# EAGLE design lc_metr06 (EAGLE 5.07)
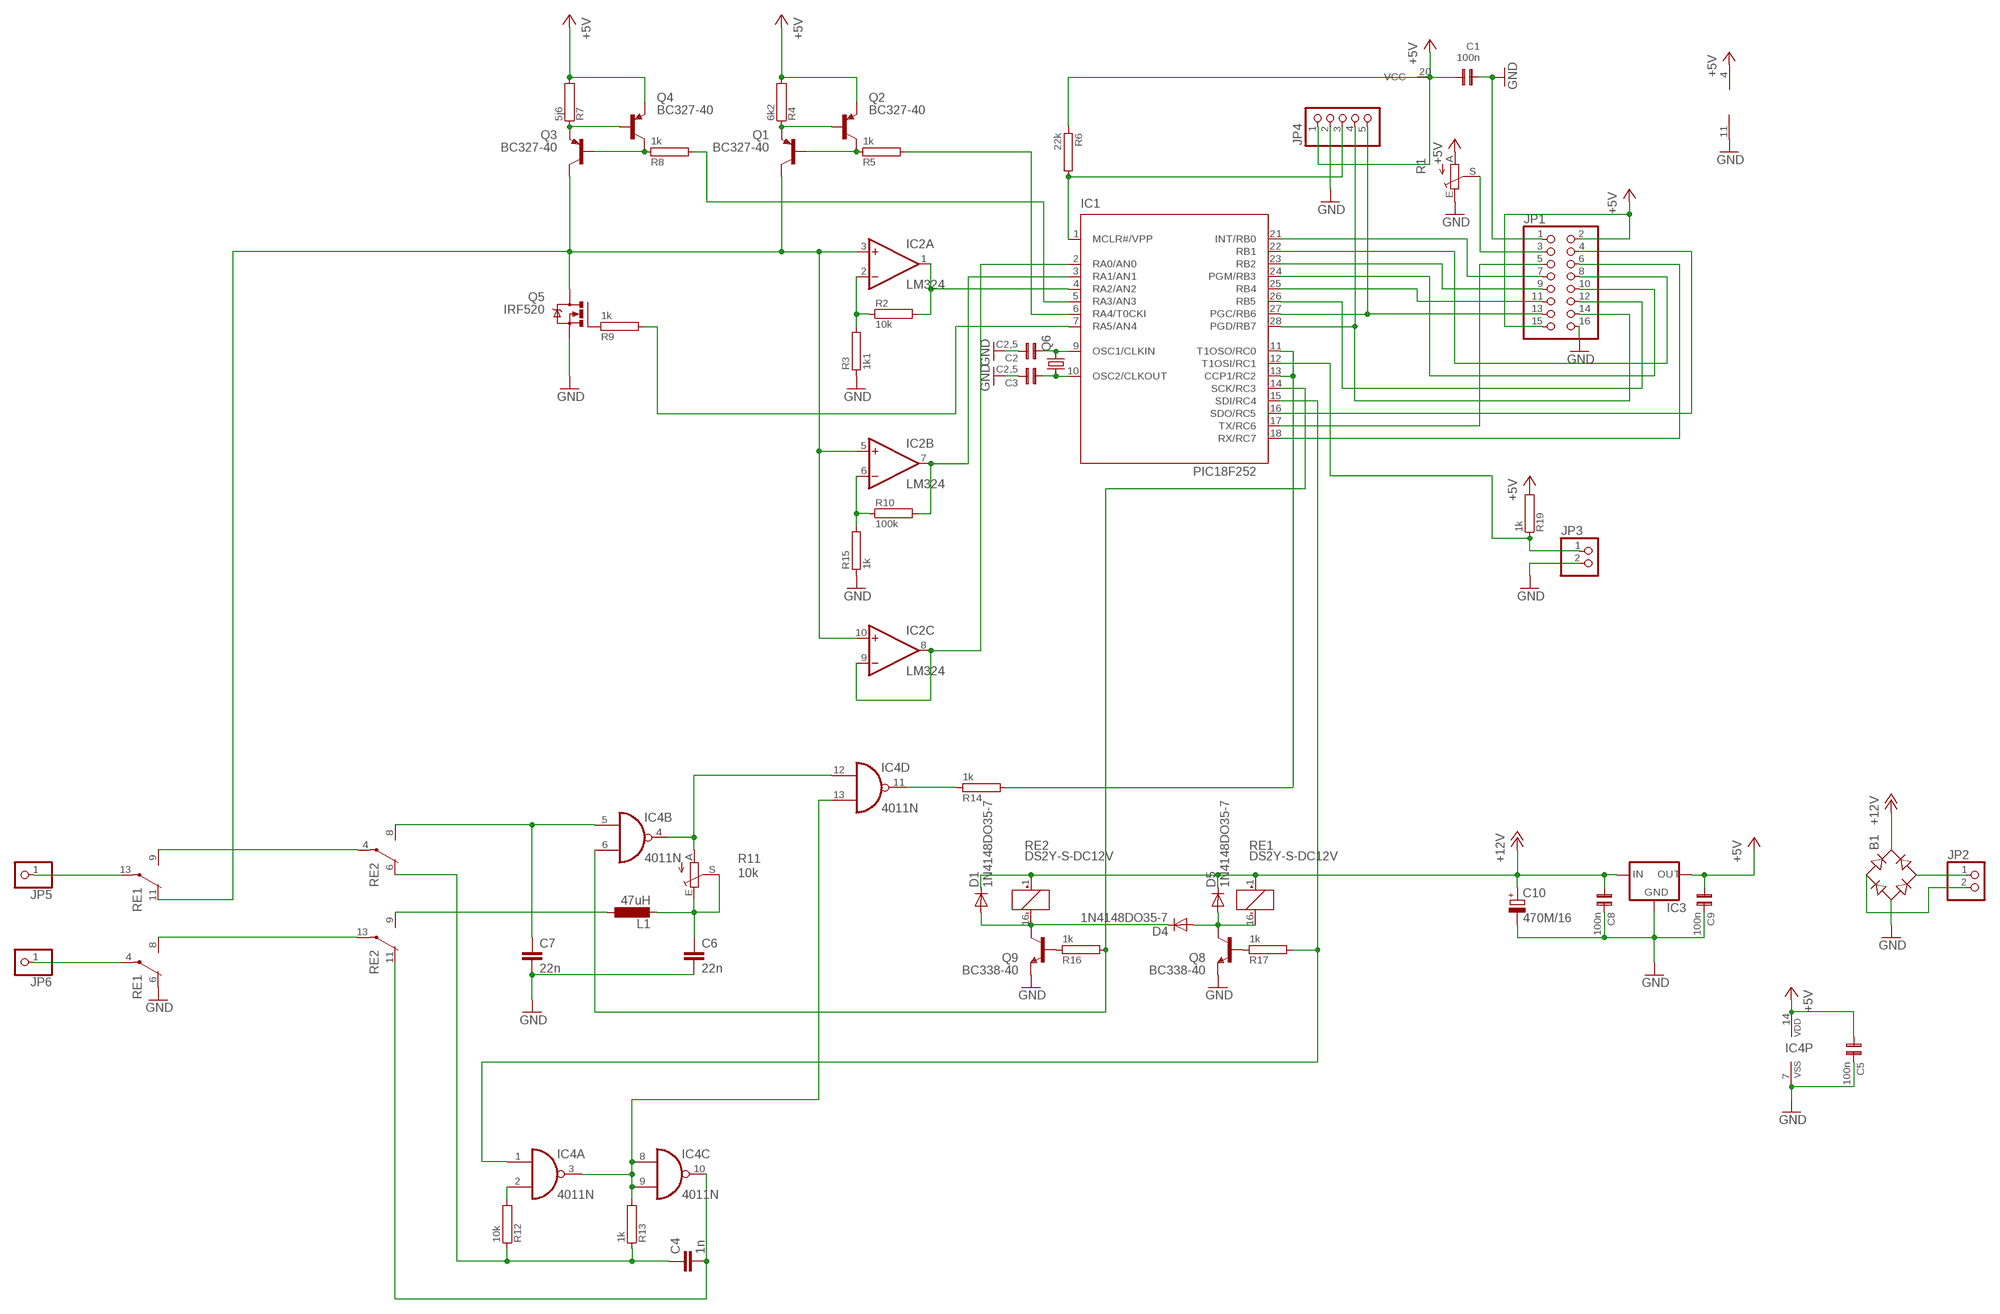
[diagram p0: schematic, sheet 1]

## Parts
B1  B-DIL  [B-DIL]
C1  100n  C2,5  [C2,5-4]
C2  C2,5  [C2,5-4]
C3  C2,5  [C2,5-4]
C4  1n  C-EU050-035X075  [C050-035X075]
C5  100n  C2,5  [C2,5-4]
C6  22n  C-EU050-035X075  [C050-035X075]
C7  22n  C-EU050-035X075  [C050-035X075]
C8  100n  C2,5  [C2,5-4]
C9  100n  C2,5  [C2,5-4]
C10  470M/16  CPOL-EUE5-10.5  [E5-10,5]
D1  1N4148DO35-7  [DO35-7]
D4  1N4148DO35-7  [DO35-7]
D5  1N4148DO35-7  [DO35-7]
IC1  PIC18F252  PIC18C252SP  [DIL28-3]
IC2  LM324  LF347N  [DIL14]
IC3  78XXS  [78XXS]
IC4  4011N  [DIL14]
JP1  PINHD-2X8  [2X08]
JP2  PINHD-1X2  [1X02]
JP3  PINHD-1X2  [1X02]
JP4  PINHD-1X5  [1X05]
JP5  PINHD-1X1  [1X01]
JP6  PINHD-1X1  [1X01]
L1  47uH  L-EUIR-2  [IR-2]
Q1  BC327-40  [TO92-EBC]
Q2  BC327-40  [TO92-EBC]
Q3  BC327-40  [TO92-EBC]
Q4  BC327-40  [TO92-EBC]
Q5  IRF520  [TO220BV]
Q6  CRYTALHC49U70  [HC49U70]
Q8  BC338-40  [TO92-EBC]
Q9  BC338-40  [TO92-EBC]
R1  TRIM_EU-ECP10S  [ECP10S]
R2  10k  0204/7  [0204/7]
R3  1k1  0204/7  [0204/7]
R4  6k2  0204/7  [0204/7]
R5  1k  0204/7  [0204/7]
R6  22k  0204/7  [0204/7]
R7  5j6  0204/7  [0204/7]
R8  1k  0204/7  [0204/7]
R9  1k  0204/7  [0204/7]
R10  100k  0204/7  [0204/7]
R11  10k  TRIM_EU-ECP10S  [ECP10S]
R12  10k  0204/7  [0204/7]
R13  1k  0204/7  [0204/7]
R14  1k  0204/7  [0204/7]
R15  1k  0204/7  [0204/7]
R16  1k  0204/7  [0204/7]
R17  1k  0204/7  [0204/7]
R19  1k  0204/7  [0204/7]
RE1  DS2Y-S-DC12V  [DS2Y]
RE2  DS2Y-S-DC12V  [DS2Y]

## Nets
+5V: C1.2 C5.1 C9.1 IC1.20(VCC) IC2.4(P:V+) IC3.OUT IC4.14(P:VDD) JP1.2 JP1.15 JP4.1 Q2.E Q4.E R1.A R4.2 R6.1 R7.2 R19.2
+12V: B1.+ C8.1 C10.+ D1.C D5.C IC3.IN RE1.1(1:+) RE2.1(1:+)
GND: B1.- C1.1 C2.2 C3.2 C5.2 C6.2 C7.2 C8.2 C9.2 C10.- IC2.11(P:V-) IC3.GND IC4.7(P:VSS) JP1.1 JP1.16 JP3.2 JP4.2 Q5.S Q8.E Q9.E R1.E R3.1 R15.1 RE1.6(2:O)
N$1: IC1.1(MCLR#/VPP) JP4.3 R6.2
N$2: JP1.3 R1.S
N$3: IC1.27(PGC/RB6) JP1.13 JP4.5
N$4: IC1.16(SDO/RC5) JP1.4
N$5: IC1.17(TX/RC6) JP1.5
N$6: IC1.18(RX/RC7) JP1.6
N$7: IC1.21(INT/RB0) JP1.7
N$8: IC1.22(RB1) JP1.8
N$9: IC1.23(RB2) JP1.9
N$10: IC1.26(RB5) JP1.12
N$11: IC1.28(PGD/RB7) JP1.14 JP4.4
N$12: IC1.24(PGM/RB3) JP1.10
N$13: IC1.25(RB4) JP1.11
N$14: IC2.2(A:-IN) R2.1 R3.2
N$15: IC1.4(RA2/AN2) IC2.1(A:OUT) R2.2
N$16: Q1.E Q2.B R4.1
N$17: Q1.B Q2.C R5.1
N$18: Q3.E Q4.B R7.1
N$19: Q3.B Q4.C R8.1
N$20: IC4.11(D:O) R14.1
N$21: IC1.6(RA4/T0CKI) R5.2
N$22: IC1.5(RA3/AN3) R8.2
N$23: Q5.G R9.1
N$24: IC1.7(RA5/AN4) R9.2
N$26: C6.1 L1.2 R11.E R11.S
N$27: IC1.11(T1OSO/RC0) IC1.13(CCP1/RC2) R14.2
N$28: IC2.6(B:-IN) R10.1 R15.2
N$29: IC1.3(RA1/AN1) IC2.7(B:OUT) R10.2
N$30: RE1.9(3:S) RE2.4(2:P)
N$31: RE1.8(2:S) RE2.13(3:P)
N$32: C2.1 IC1.9(OSC1/CLKIN) Q6.2
N$33: C3.1 IC1.10(OSC2/CLKOUT) Q6.1
N$34: C7.1 IC4.5(B:I0) RE2.8(2:S)
N$35: L1.1 RE2.9(3:S)
N$36: IC4.4(B:O) IC4.12(D:I0) R11.A
N$37: IC2.3(A:+IN) IC2.5(B:+IN) IC2.10(C:+IN) Q1.C Q3.C Q5.D RE1.11(3:O)
N$38: D4.A D5.A Q8.C RE1.16(1:-)
N$39: D1.A D4.C Q9.C RE2.16(1:-)
N$40: IC1.12(T1OSI/RC1) JP3.1 R19.1
N$41: B1.AC2 JP2.1
N$42: Q9.B R16.1
N$43: Q8.B R17.1
N$45: IC1.15(SDI/RC4) IC4.1(A:I0) R17.2
N$46: IC1.14(SCK/RC3) IC4.6(B:I1) R16.2
N$47: IC1.2(RA0/AN0) IC2.8(C:OUT) IC2.9(C:-IN)
N$48: B1.AC1 JP2.2
N$64: IC4.3(A:O) IC4.8(C:I0) IC4.9(C:I1) IC4.13(D:I1) R13.2
N$65: C4.2 IC4.10(C:O) RE2.11(3:O)
N$66: IC4.2(A:I1) R12.2
N$67: C4.1 R12.1 R13.1 RE2.6(2:O)
N$70: JP6.1 RE1.4(2:P)
N$71: JP5.1 RE1.13(3:P)
Unconnected: IC2.12(D:+IN) IC2.13(D:-IN) IC2.14(D:OUT)

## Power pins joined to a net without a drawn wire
GND: IC1.8(GND) IC1.19(GND)

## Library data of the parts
B1 = rectifier:B-DIL: RECTIFIER
C1-C3 C5 C8 C9 = CAP:C2,5
C4 C6 C7 = rcl:C-EU: CAPACITOR, European symbol
C10 = rcl:CPOL-EU: POLARIZED CAPACITOR, European symbol
D1 D4 D5 = diode:1N4148: DIODE
IC1 = micro-pic18xxx:PIC18C2*2?: High-Performance Microcontrollers with 10-Bit A/D
IC2 = linear:LF347: OP AMP
IC3 = v-reg:78XXS: VOLTAGE REGULATOR
IC4 = 40xx:4011: Quad 2-input NAND
JP1 = pinhead:PINHD-2X8: PIN HEADER
JP2 JP3 = pinhead:PINHD-1X2: PIN HEADER
JP4 = pinhead:PINHD-1X5: PIN HEADER
JP5 JP6 = pinhead:PINHD-1X1: PIN HEADER
L1 = rcl:L-EU: INDUCTOR, European symbol
Q1-Q4 = transistor-pnp:BC327*: PNP Transistror
Q5 = transistor-power:IRF520: HEXFET Power MOSFET
Q6 = crystal:CRYTAL: CRYSTAL
Q8 Q9 = transistor-npn:BC338*: NPN Transistor
R1 R11 = pot:TRIM_EU-: POTENTIOMETER
R2-R10 R12-R17 R19 = R:0204/7
RE1 RE2 = relay:DS2Y-S-DC*: MINIATURE RELAY NAiS Source: http://www.mew-europe.com/.. en_ds_61005_0023.pdf

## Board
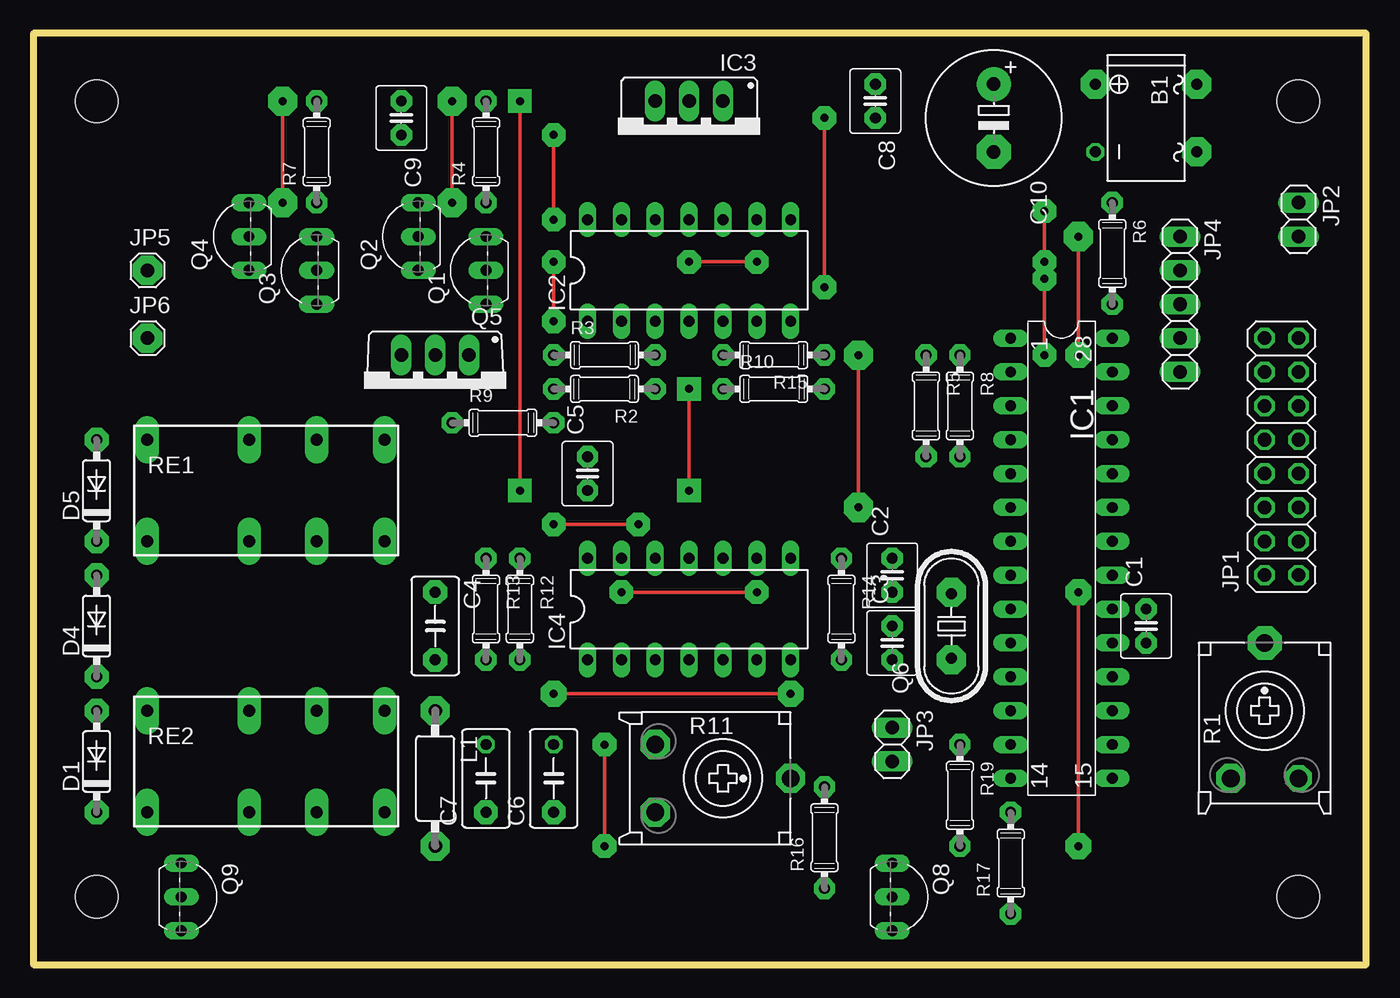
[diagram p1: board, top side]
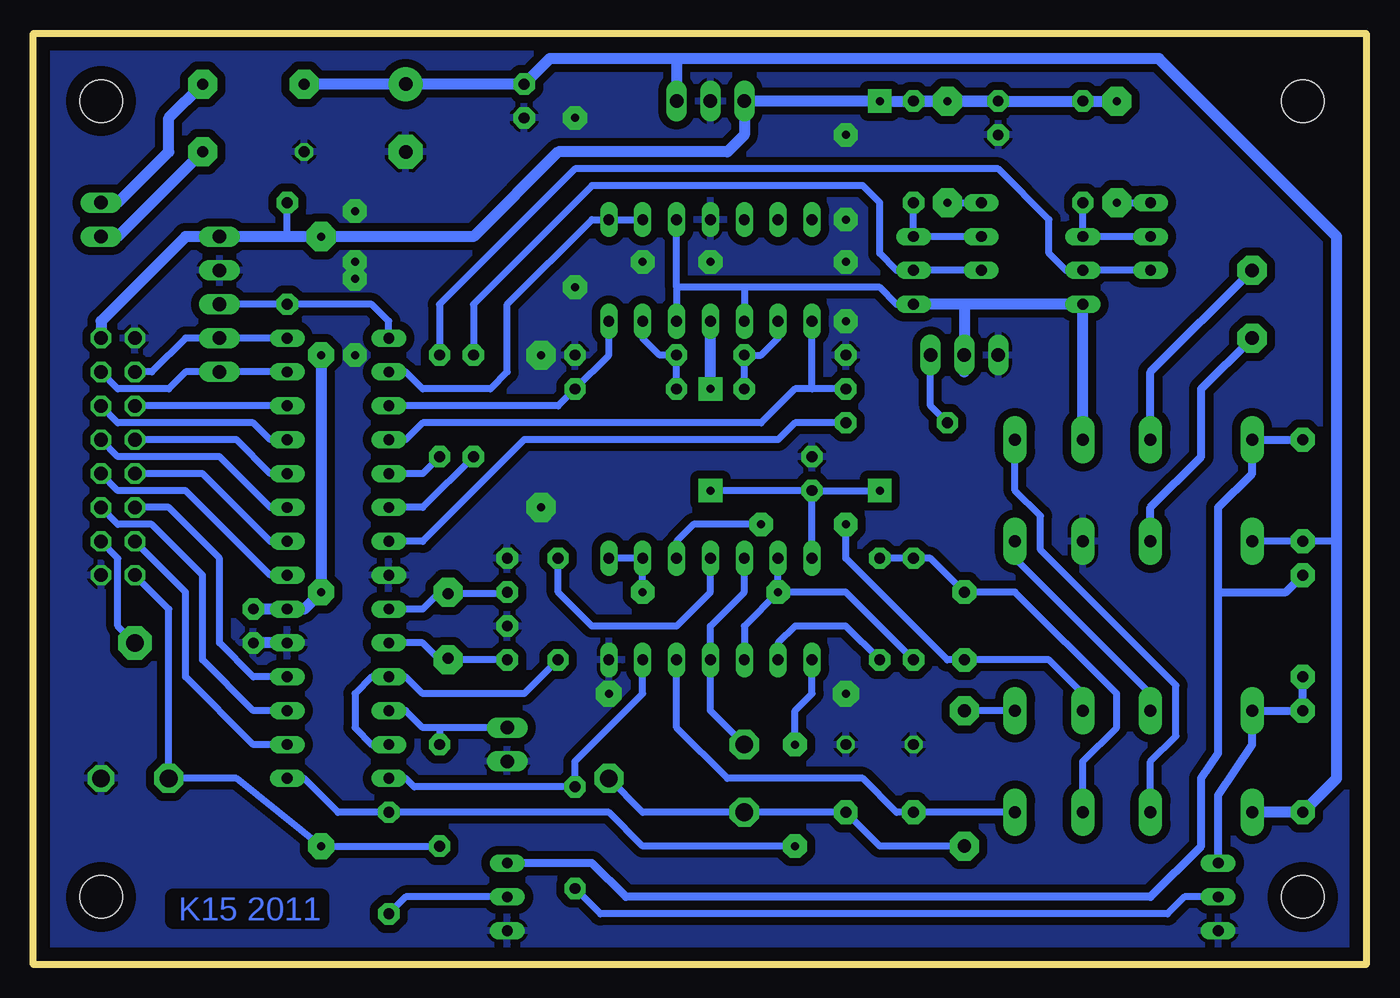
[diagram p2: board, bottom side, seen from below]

Size 100 x 69.84 mm. Coordinates in mm from the lower left corner, seen from the top.
Outline: 100,69.84 0,69.84 0,0 100,0 100,69.84
Copper layers (1*16): Top 0.035mm / dielectric 1.5mm / Bottom 0.035mm
Design rules "default": minimum track width 10mil, minimum drill 24mil, track to track 8mil, track to pad 8mil, pad to pad 8mil, via to via 8mil, smd to smd 8mil, copper to edge 40mil, drill to drill 8mil, minimum pad ring 10mil, minimum via ring 8mil, stop-mask expansion 4mil, vias tented up to drill 0mil, thermal gap 10mil
Holes 3.2 mm at 94.92,5.07 94.92,64.76 4.75,5.07 4.75,64.76

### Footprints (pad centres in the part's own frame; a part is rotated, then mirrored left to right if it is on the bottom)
B-DIL = drill 0.813 round: + -2.54,-3.81 | drill 0.813 octagon: - 2.54,-3.81; AC1 2.54,3.81; AC2 -2.54,3.81
C2,5-4 = drill 0.813 pad 1.6 octagon: 1 -1.27,0; 2 1.27,0
C050-035X075 = drill 0.813 octagon: 1 -2.54,0; 2 2.54,0
E5-10,5 = drill 1.016 pad 2.54 round: + -2.54,0 | drill 1.016 pad 2.54 octagon: - 2.54,0
DO35-7 = drill 0.813 pad 1.778 octagon: A 3.81,0; C -3.81,0
DIL28-3 = drill 0.813 long: 1 -16.51,-3.81; 2 -13.97,-3.81; 3 -11.43,-3.81; 4 -8.89,-3.81; 5 -6.35,-3.81; 6 -3.81,-3.81; 7 -1.27,-3.81; 8 1.27,-3.81; 9 3.81,-3.81; 10 6.35,-3.81; 11 8.89,-3.81; 12 11.43,-3.81; 13 13.97,-3.81; 14 16.51,-3.81; 15 16.51,3.81; 16 13.97,3.81; 17 11.43,3.81; 18 8.89,3.81; 19 6.35,3.81; 20 3.81,3.81; 21 1.27,3.81; 22 -1.27,3.81; 23 -3.81,3.81; 24 -6.35,3.81; 25 -8.89,3.81; 26 -11.43,3.81; 27 -13.97,3.81; 28 -16.51,3.81
DIL14 = drill 0.813 long: 1 -7.62,-3.81; 2 -5.08,-3.81; 3 -2.54,-3.81; 4 0,-3.81; 5 2.54,-3.81; 6 5.08,-3.81; 7 7.62,-3.81; 8 7.62,3.81; 9 5.08,3.81; 10 2.54,3.81; 11 0,3.81; 12 -2.54,3.81; 13 -5.08,3.81; 14 -7.62,3.81
78XXS = drill 1.016 long: GND 0,-2.54; IN -2.54,-2.54; OUT 2.54,-2.54
2X08 = drill 1.016 octagon: 1 -8.89,-1.27; 2 -8.89,1.27; 3 -6.35,-1.27; 4 -6.35,1.27; 5 -3.81,-1.27; 6 -3.81,1.27; 7 -1.27,-1.27; 8 -1.27,1.27; 9 1.27,-1.27; 10 1.27,1.27; 11 3.81,-1.27; 12 3.81,1.27; 13 6.35,-1.27; 14 6.35,1.27; 15 8.89,-1.27; 16 8.89,1.27
1X02 = drill 1.016 long: 1 -1.27,0; 2 1.27,0
1X05 = drill 1.016 long: 1 -5.08,0; 2 -2.54,0; 3 0,0; 4 2.54,0; 5 5.08,0
1X01 = drill 1.016 octagon: 1 0,0
IR-2 = drill 1 pad 1.676 round: 1 -5.08,0; 2 5.08,0
TO92-EBC = drill 0.813 long: B 0,-1.27; C -2.54,-1.27; E 2.54,-1.27
TO220BV = drill 1.016 long: D 0,-2.54; G -2.54,-2.54; S 2.54,-2.54
HC49U70 = drill 0.813 round: 1 -2.413,0; 2 2.413,0
ECP10S = drill 1.321 octagon: A -2.54,-5.08; E 2.54,-5.08; S 0,5.08
0204/7 = drill 0.813 pad 1.6 octagon: 1 -3.81,0; 2 3.81,0
DS2Y = drill 0.9 pad 1.778 long: 1 -8.89,-3.81; 4 -1.27,-3.81; 6 3.81,-3.81; 8 8.89,-3.81; 9 8.89,3.81; 11 3.81,3.81; 13 -1.27,3.81; 16 -8.89,3.81

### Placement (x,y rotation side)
B1  83.49,63.49 270 top
C1  83.49,25.39 90 top
C2  64.44,29.2 90 top
C3  64.44,24.12 90 top
C4  30.15,25.39 270 top
C5  41.58,36.82 90 top
C6  39.04,13.96 90 top
C7  33.96,13.96 90 top
C8  63.17,64.76 270 top
C9  27.61,63.49 270 top
C10  72.06,63.49 270 top
D1  4.75,15.23 90 top
D4  4.75,25.39 90 top
D5  4.75,35.55 90 top
IC1  77.14,30.47 270 top
IC2  49.2,52.06 0 top
IC3  49.2,62.22 180 top
IC4  49.2,26.66 0 top
JP1  93.65,38.09 90 top
JP2  94.92,55.87 270 top
JP3  64.44,16.5 270 top
JP4  86.03,49.52 270 top
JP5  8.56,52.06 0 top
JP6  8.56,46.98 0 top
L1  30.15,13.96 270 top
Q1  32.69,52.06 90 top
Q2  27.61,54.6 90 top
Q3  19.99,52.06 90 top
Q4  14.91,54.6 90 top
Q5  30.15,43.17 180 top
Q6  68.89,25.39 90 top
Q8  65.71,5.07 270 top
Q9  12.37,5.07 270 top
R1  92.38,19.04 0 top
R2  42.85,43.17 180 top
R3  42.85,45.71 0 top
R4  33.96,60.95 90 top
R5  66.98,41.9 270 top
R6  80.95,53.33 270 top
R7  21.26,60.95 90 top
R8  69.52,41.9 270 top
R9  35.23,40.63 0 top
R10  55.55,43.17 0 top
R11  51.74,13.96 270 top
R12  36.5,26.66 270 top
R13  33.96,26.66 270 top
R14  60.63,26.66 270 top
R15  55.55,45.71 180 top
R16  59.36,9.52 90 top
R17  73.33,7.61 90 top
R19  69.52,12.69 270 top
RE1  17.45,35.55 0 top
RE2  17.45,15.23 0 top

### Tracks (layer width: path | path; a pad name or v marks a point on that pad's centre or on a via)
+5V  (via drill 0.6 pad 1.78, 0.6 pad 1.93, 0.6 pad 2.18)
  Top 0.254: v18.72,64.76 v18.72,57.14 | v31.42,64.76 v31.42,57.14 | v78.41,54.6 v78.41,45.71 | v78.41,27.93 v78.41,8.88 | v36.5,35.55 v36.5,64.76 | v49.2,35.55 v49.2,43.17
  Bottom 0.508: C1.2 IC1.20 | v18.72,57.14 Q4.E | 80.95,54.6 R6.1 | v31.42,57.14 Q2.E | JP1.2 89.84,26.66 R1.A 84.76,13.96 v78.41,8.88 R19.2 | C5.1 v36.5,35.55 | C5.1 v49.2,35.55 | IC4.14 C5.1
  Bottom 0.813: JP1.15 94.92,48.25 88.57,54.6 JP4.1 80.95,54.6 v78.41,54.6 66.98,54.6 60.63,60.95 47.93,60.95 46.66,62.22 IC3.OUT v36.5,64.76 C9.1 R4.2 v31.42,64.76 R7.2 v18.72,64.76 | C1.2 79.68,26.66 v78.41,27.93 v78.41,45.71 | v49.2,43.17 IC2.4
+12V
  Bottom 0.508: RE1.1 D5.C 2.21,31.74
  Bottom 0.813: B1.+ C10.+ C8.1 61.27,67.93 51.74,67.93 | RE2.1 D1.C 2.21,13.96 2.21,31.74 2.21,54.6 15.54,67.93 51.74,67.93 | 51.74,67.93 IC3.IN
GND  (via drill 0.6 pad 1.78, 0.6 pad 1.93, 0.6 pad 2.18)
  Top 0.254: v61.9,34.28 v61.9,45.71 | v75.87,52.7 v75.87,56.51 | v75.87,45.71 v75.87,51.43 | v49.2,52.7 v54.28,52.7 | v39.04,48.25 v39.04,52.7 | v39.04,55.87 v39.04,62.22 | v59.36,50.79 v59.36,63.49 | v39.04,20.31 v56.82,20.31
  Bottom 0.813: IC1.19 C1.1
  pour Bottom (isolate 0.61): 100,-0.01 0.94,-0.01 0.94,69.84 100,69.84
N$1
  Bottom 0.508: IC1.1 73.33,48.25 74.6,49.52 R6.2 JP4.3
N$2
  Bottom 0.508: R1.S 93.65,25.39 93.65,30.47 JP1.3
N$3
  Bottom 0.508: IC1.27 JP4.5 88.57,44.44 89.84,43.17 93.65,43.17 JP1.13
N$4
  Bottom 0.508: IC1.16 83.49,16.5 88.57,21.58 88.57,27.93 JP1.4
N$5
  Bottom 0.508: IC1.17 83.49,19.04 87.3,22.85 87.3,29.2 91.11,33.01 93.65,33.01 JP1.5
N$6
  Bottom 0.508: IC1.18 83.49,21.58 86.03,24.12 86.03,30.47 89.84,34.28 JP1.6
N$7
  Bottom 0.508: IC1.21 82.22,29.2 88.57,35.55 93.65,35.55 JP1.7
N$8
  Bottom 0.508: IC1.22 82.22,31.74 87.3,36.82 JP1.8
N$9
  Bottom 0.508: IC1.23 82.22,34.28 86.03,38.09 93.65,38.09 JP1.9
N$10
  Bottom 0.508: IC1.26 JP1.12
N$11
  Bottom 0.508: IC1.28 JP4.4 88.57,46.98 91.11,44.44 JP1.14
N$12
  Bottom 0.508: IC1.24 82.22,36.82 84.76,39.36 JP1.10
N$13
  Bottom 0.508: IC1.25 82.22,39.36 83.49,40.63 93.65,40.63 JP1.11
N$14
  Bottom 0.508: IC2.2 44.12,46.98 45.39,45.71 R3.2 R2.1
N$15
  Bottom 0.508: IC1.4 72.06,39.36 70.79,40.63 45.39,40.63 42.85,43.17 41.58,43.17 | 41.58,43.17 IC2.1 | R2.2 41.58,43.17
N$16
  Bottom 0.508: Q2.B Q1.E R4.1
N$17
  Bottom 0.508: Q2.C Q1.B 35.23,52.06 36.5,53.33 36.5,57.14 37.77,58.41 58.09,58.41 66.98,49.52 R5.1
N$18
  Bottom 0.508: Q4.B Q3.E R7.1
N$19
  Bottom 0.508: R8.1 69.52,49.52 59.36,59.68 27.61,59.68 23.8,55.87 23.8,53.33 22.53,52.06 Q3.B Q4.C
N$20
  Bottom 0.508: R14.1 60.63,27.93 58.09,25.39 51.74,25.39 49.2,27.93 IC4.11
N$21
  Bottom 0.508: IC1.6 70.79,34.28 R5.2
N$22
  Bottom 0.508: R8.2 70.79,36.82 IC1.5
N$23
  Bottom 0.508: R9.1 32.69,41.9 Q5.G
N$24
  Bottom 0.508: IC1.7 70.79,31.74 63.17,39.36 44.12,39.36 42.85,40.63 R9.2
N$25  (via drill 0.6 pad 2.18)
  other vias: 30.15,19.04
N$26
  Bottom 0.508: L1.2 36.5,8.88 C6.1 R11.E 54.28,11.42 R11.S
N$27
  Bottom 0.508: IC1.13 74.6,16.5 75.87,17.77 75.87,20.31 74.6,21.58 IC1.11 72.06,21.58 70.79,20.31 63.17,20.31 R14.2
N$28
  Bottom 0.508: IC2.6 54.28,46.98 53.01,45.71 R15.2 R10.1
N$29
  Bottom 0.508: IC2.7 56.82,45.71 R10.2 60.63,41.9 IC1.3
N$30
  Bottom 0.508: RE2.4 16.18,15.23 14.28,17.13 14.28,20.94 24.44,31.1 24.44,33.65 26.34,35.55 RE1.9
N$31
  Bottom 0.508: RE2.13 16.18,20.31 26.34,30.47 RE1.8
N$32
  Bottom 0.508: IC1.9 70.79,26.66 69.52,27.93 68.38,27.93 Q6.2 64.57,27.8 C2.1
N$33
  Bottom 0.508: IC1.10 70.79,24.12 69.52,22.85 | C3.1 69.52,22.85 | Q6.1 69.39,22.98 69.52,22.85
N$34
  Bottom 0.508: IC4.5 51.74,17.77 47.93,13.96 37.77,13.96 35.23,11.42 C7.1 RE2.8
N$35
  Bottom 0.508: RE2.9 L1.1
N$36
  Bottom 0.508: IC4.12 46.66,27.93 49.2,25.39 IC4.4 49.2,19.04 R11.A
N$37
  Bottom 0.508: 51.74,50.79 IC2.10 | 51.74,50.79 IC2.5 | 46.66,50.79 IC2.3 | 46.66,50.79 51.74,50.79 | Q1.C 35.23,49.52 36.5,50.79 46.66,50.79
  Bottom 0.813: 30.15,49.52 Q1.C | 30.15,49.52 Q5.D 30.15,44.44 | RE1.11 Q3.C 30.15,49.52
N$38
  Bottom 0.61: Q8.C 58.09,7.61 55.55,5.07 16.18,5.07 12.37,8.88 12.37,13.96 11.1,15.87 11.1,27.93 | D5.A RE1.16 8.56,36.82 11.1,34.28 11.1,27.93 | 11.1,27.93 6.02,27.93 D4.A
N$39
  Bottom 0.61: Q9.C 11.1,12.69 8.56,16.5 RE2.16 D1.A D4.C
N$40
  Bottom 0.508: JP3.1 69.52,17.77 | 69.52,17.77 70.79,17.77 72.06,19.04 IC1.12 | 69.52,17.77 R19.1
N$41
  Bottom 0.813: B1.AC2 89.84,63.49 89.84,60.95 93.65,57.14 JP2.1
N$42
  Bottom 0.508: Q9.B 13.64,5.07 14.91,3.8 57.45,3.8 R16.1
N$43
  Bottom 0.508: R17.1 72.06,5.07 Q8.B
N$44  (via drill 0.6 pad 2.18)
  other vias: 30.15,8.88
N$45  (via drill 0.6 pad 1.78)
  Top 0.254: v42.85,8.88 v42.85,16.5
  Bottom 0.508: IC1.15 79.68,13.96 77.14,11.42 R17.2 56.82,11.42 54.28,8.88 v42.85,8.88 | v42.85,16.5 42.85,19.04 41.58,20.31 IC4.1
N$46
  Bottom 0.508: IC1.14 72.06,13.96 71.42,13.33 R16.2 59.36,15.23 54.28,20.31 IC4.6
N$47
  Bottom 0.508: IC2.9 IC2.8 58.09,55.87 64.44,49.52 64.44,44.44 65.71,43.17 70.79,43.17 72.06,44.44 IC1.2
N$48
  Bottom 0.813: B1.AC1 93.65,54.6 JP2.2
N$49  (via drill 0.6 pad 2.18)
  other vias: 87.3,66.03
N$50  (via drill 0.6 pad 2.18)
  other vias: 87.3,60.95
N$51  (via drill 0.6 pad 2.18)
  other vias: 79.68,66.03
N$52  (via drill 0.6 pad 2.18)
  other vias: 46.66,16.5
N$53  (via drill 0.6 pad 2.18)
  other vias: 46.66,11.42
N$54  (via drill 0.6 pad 2.18)
  other vias: 56.82,13.96
N$55  (via drill 0.6 pad 2.18)
  other vias: 8.56,52.06
N$56  (via drill 0.6 pad 2.18)
  other vias: 68.89,27.93
N$57  (via drill 0.6 pad 2.18)
  other vias: 68.89,22.85
N$58  (via drill 0.6 pad 2.18)
  other vias: 8.56,46.98
N$59  (via drill 0.6 pad 1.78)
  other vias: 33.96,11.42
N$60  (via drill 0.6 pad 1.78)
  other vias: 39.04,11.42
N$61  (via drill 0.6 pad 2.54)
  other vias: 92.38,24.12
N$62  (via drill 0.6 pad 1.78)
  other vias: 30.15,27.93
N$63  (via drill 0.6 pad 1.78)
  other vias: 30.15,22.85
N$64  (via drill 0.6 pad 1.78)
  Top 0.254: v44.12,27.93 v54.28,27.93
  Bottom 0.508: v44.12,27.93 39.04,27.93 R13.2 | v44.12,27.93 46.66,25.39 IC4.3 | v44.12,27.93 IC4.13 | v54.28,27.93 IC4.9 IC4.8
N$65  (via drill 0.6 pad 1.78)
  Top 0.254: v39.04,33.01 v45.39,33.01
  Bottom 0.508: v39.04,33.01 39.04,30.47 31.42,22.85 C4.2 23.8,22.85 21.26,20.31 RE2.11 | v45.39,33.01 50.47,33.01 51.74,31.74 IC4.10
N$66
  Bottom 0.508: R12.2 39.04,25.39 42.85,25.39 44.12,24.12 IC4.2
N$67
  Bottom 0.508: R12.1 R13.1 32.69,30.47 C4.1 26.34,27.93 18.72,20.31 18.72,17.77 21.26,15.23 RE2.6
N$68  (via drill 0.6 pad 2.18)
  other vias: 89.84,13.96
N$70
  Bottom 0.61: RE1.4 16.18,34.28 12.37,38.09 12.37,43.17 JP6.1
N$71
  Bottom 0.61: RE1.13 16.18,44.44 JP5.1

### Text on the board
Bottom: K15 2011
